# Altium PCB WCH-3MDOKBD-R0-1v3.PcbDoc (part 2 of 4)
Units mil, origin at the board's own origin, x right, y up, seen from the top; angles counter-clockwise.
Board outline 11710.74 x 4477.49 mil, 2 copper layers (Top Layer, Bottom Layer); 233 components, 145 nets, 545 pads, 1448 vias.
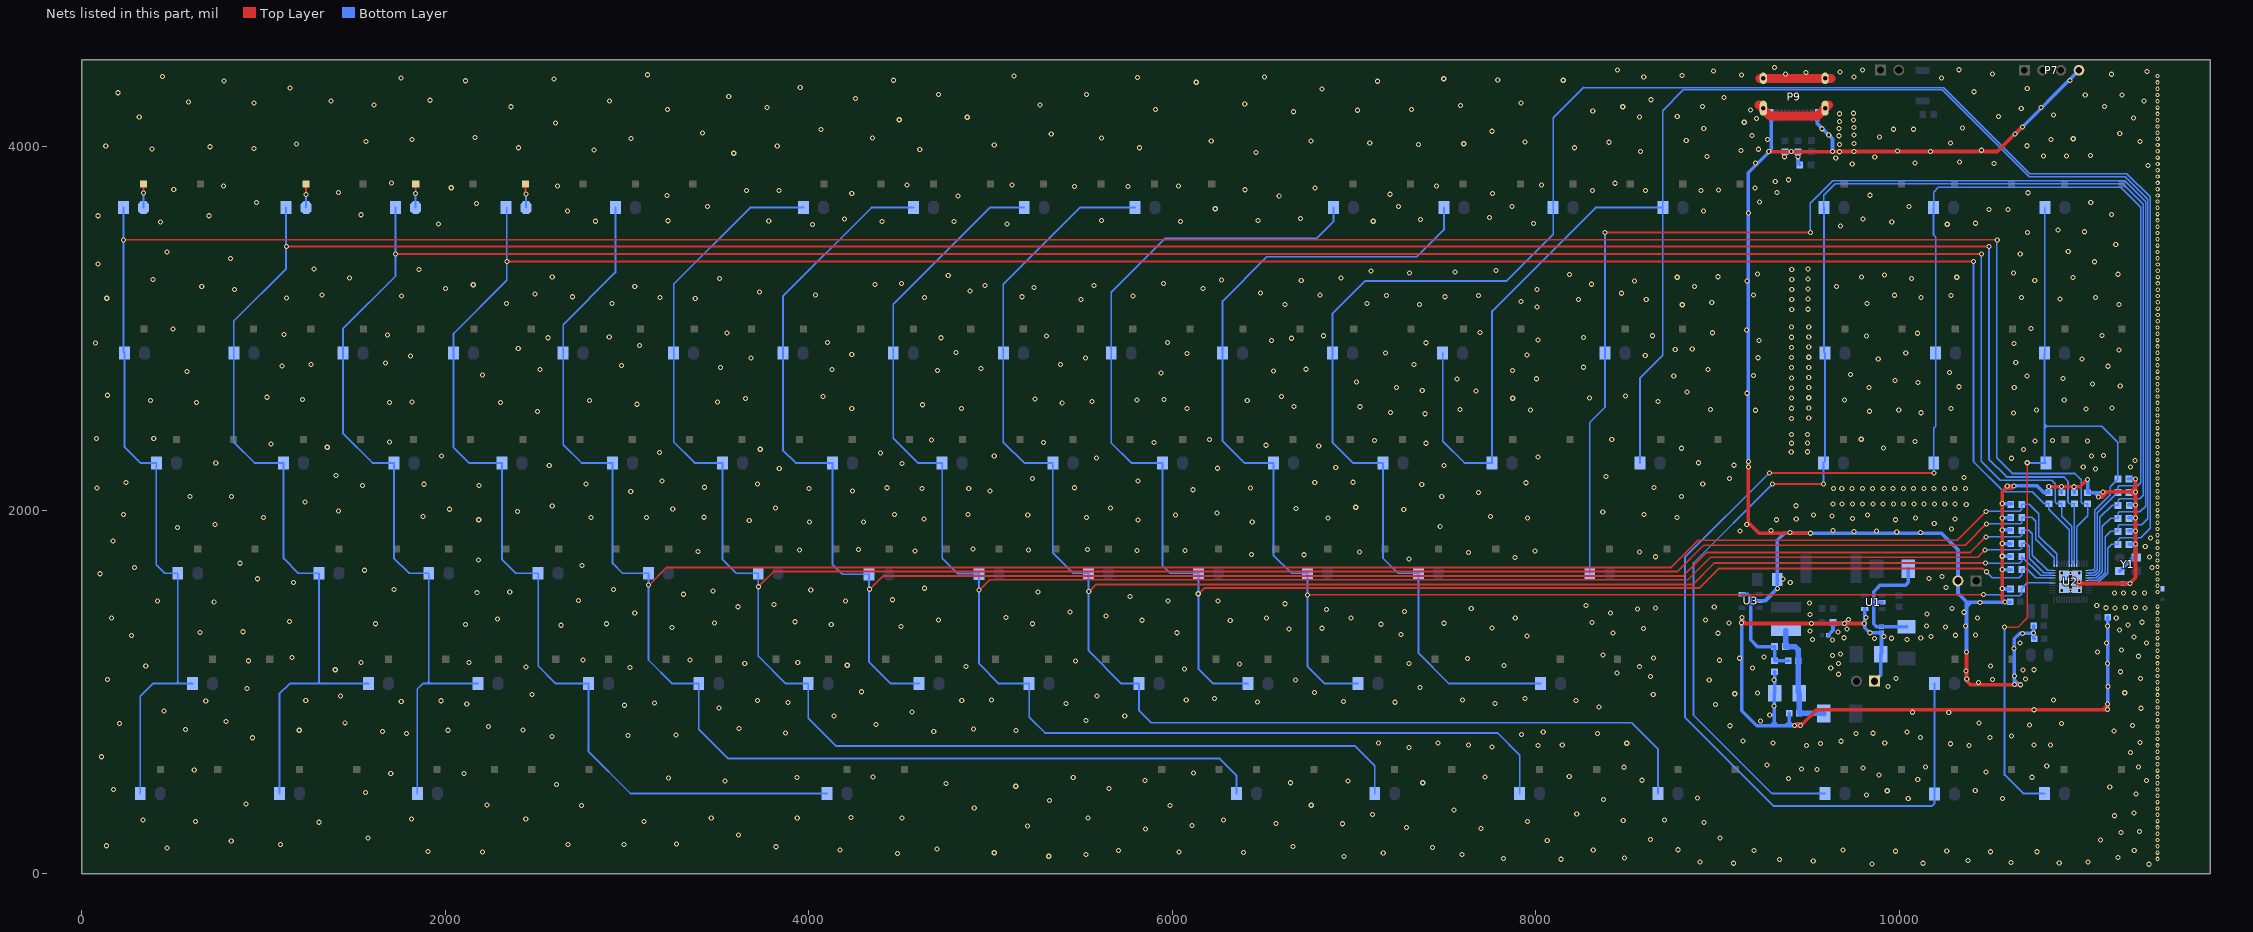
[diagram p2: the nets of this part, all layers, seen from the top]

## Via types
v1: diameter 28, hole 16, Top Layer to Bottom Layer, tented both sides, 1320 vias
v2: diameter 24, hole 12, Top Layer to Bottom Layer, tented both sides, 128 vias

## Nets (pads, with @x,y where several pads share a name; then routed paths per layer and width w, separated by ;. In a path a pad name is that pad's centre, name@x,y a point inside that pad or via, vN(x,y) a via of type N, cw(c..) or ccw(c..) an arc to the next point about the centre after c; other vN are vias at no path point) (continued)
BT-: C2.1 C3.1 C5.1 C6.1 C7.1 C8.1 C9.1 C11.2 C12.2 C13.2 C14.1 E1.0 J1.1 P7.4 P8.2 P9.0 P9.A1 P9.B1 R10.2 R11.2 R128.1 R129.1 R133.1 RJ1.1 RJ2.1 RJ3.1 RJ4.1 RJ5.1 RJ6.1 RJ7.1 RJ8.1 RJ9.1 RJ10.1 RJ11.1 RJ12.1 RJ13.1 RJ14.1 RJ15.1 RJ16.1 RJ17.1 U1.4 U2.0 U3.2 Y1.2 Y1.4 | length 18000.2
  Top Layer w20: v1(9134.61,1409.74) 9134.61,1395.68 ; v1@9168.65,2267.26 9168.65,1931.1 9227.54,1872.21 v1(9511.69,1872.21) ; v1(9281,3971.58) v1(9404.61,3971.58) v1@9636.45,3971.58 ; v1@9456.96,813.86 v1@9457.07,813.97 ; v1@9634.7,3972.2 10538.09,3972.2 v1@10675.48,4109.58 ; v1(9806.35,1376.09) v1(9697.77,1376.09) 9154.21,1376.09 ; v1(10368.6,1218.87) 10368.6,1061.6 10391.09,1039.11 v1@10670.69,1039.11 ; v1(10579.88,1493.79) 10565.71,1507.95 v1(10565.71,1567.63) v1(10565.71,1671.91) v1(10565.71,1745.7) v1(10565.71,1814.83) v1(10565.71,1890.97) v1(10565.71,1956.97) v1(10565.71,2035.15) 10565.71,2100.44 v1@10586.22,2120.95 ; v1(10593.28,2131.64) v1@10628.4,2131.64 ; v1@10595.1,2129.83 v1@10586.22,2120.95 ; v1(10629.12,2132.36) v1@10628.4,2131.64 ; v1(10821.17,2128.76) 10993.8,2128.76 v1(11034.05,2169.01) ; 10978.98,1596.12 11003.83,1596.12 ; v2@10988.26,1611.7 11003.83,1596.12 ; 10991.91,1584.2 11003.83,1596.12 ; v1@11120.34,2100.12 v1@11125.31,2100.12 ; v1(11145.36,934.11) v1@11145.36,926.02 ; v1(11298.76,2171.58) 11298.76,2124.66 ; 9134.61,1395.68 9134.61,1379.16 9131.54,1376.09 9154.21,1376.09 ; 9134.61,1395.68 9154.21,1376.09 ; v1@9457.07,813.97 v1(9423.52,813.97) 9434.27,824.73 9467.83,824.73 ; v1@9457.07,813.97 9467.83,824.73 ; 9467.83,824.73 9543.56,900.46 11119.8,900.46 ; v1@10586.22,2120.95 10617.7,2120.95 v1@10628.4,2131.64 ; 11003.83,1596.12 v1(11267.28,1596.12) 11298.76,1627.61 v1(11298.76,1814.3) v1(11298.76,1885.75) v1(11298.76,1957.21) v1(11298.76,2028.66) 11298.76,2075.34 ; 11119.8,900.46 v1@11145.36,926.02 ; 11119.8,900.46 11148.48,900.46 11145.36,903.58 v1@11145.36,926.02 ; v1@11125.31,2100.12 v1(11095.82,2070.63) 11116.06,2070.63 11145.55,2100.12 ; v1@11125.31,2100.12 11145.55,2100.12 ; 11145.55,2100.12 11273.98,2100.12 ; 11273.98,2100.12 11298.76,2075.34 ; 11273.98,2100.12 11274.22,2100.12 ; 11274.22,2100.12 11298.76,2124.66 ; 11274.22,2100.12 v1(11298.76,2100.12) ; 11298.76,2075.34 v1(11298.76,2100.12) ; v1(11298.76,2100.12) 11298.76,2124.66
  Top Layer w50: 9228.25,4229.01 9289.92,4167.33 9547.79,4167.33 P9.0@9608.53,4228.08 ; P9.0@9233.05,4374.91 P9.0@9251.14,4374.91 P9.0@9591.3,4374.91 9622.76,4374.91
  Bottom Layer w20: v1(9131.93,1379.85) v1@9131.93,1409.74 ; v1@9131.93,1380.56 9131.93,896.43 9214.5,813.86 9293.36,813.86 ; v1@9168.14,2236.74 9168.14,2989.83 9168.14,3259.66 9168.14,3855.24 9294.26,3981.36 P9.A1@9294.26,4172.15 ; U3.2@9228.25,1500.05 9260.48,1500.05 v1(9328.59,1568.15) C13.2@9328.59,1617.07 ; R133.1@9313.87,1111.26 9313.87,992.47 C12.2@9313.23,991.82 9310.83,989.42 9310.83,831.33 ; C13.2@9331.11,1614.55 C13.2@9328.59,1617.07 ; v1@9370.04,3942.53 R10.2@9370.04,3970.81 9370.94,3971.71 R11.2@9442.13,3971.71 v1@9442.13,3943.81 ; C11.2@9393.12,881.12 9393.12,832.42 ; v1(9442.47,3943.47) v1@9442.13,3943.81 ; R128.1@9452.55,3898.85 9442.13,3909.27 v1@9442.13,3943.81 ; v1@9456.96,813.86 v1@9411.68,813.86 ; P9.B1@9548.19,4172.15 9548.19,4125.84 9631.52,4042.51 v1@9631.52,3971.58 ; C5.1@9607.68,1311.74 9634.85,1338.91 R129.1@9634.85,1380.06 9635.78,1381 9640.69,1376.09 v1@9697.54,1376.09 ; v1(9697.77,1376.09) v1@9697.54,1376.09 ; v1(9720.27,1398.81) v1@9697.54,1376.09 ; U1.4@9809.52,1455.37 9809.52,1352.67 v1(9837.07,1325.11) C3.1@9901.41,1325.11 9901.41,1209.4 C2.1@9898.17,1206.15 9898.17,1093.77 J1.1@9863.17,1058.77 ; v1(10368.6,1218.87) 10368.6,1469.66 ; v1(10565.71,1567.63) 10567.31,1566.03 RJ11.1@10610.94,1566.03 ; v1(10565.71,1671.91) RJ10.1@10613.36,1671.91 ; v1(10565.71,1745.7) RJ9.1@10612.78,1745.7 ; v1(10565.71,1814.83) RJ8.1@10611.38,1814.83 ; v1(10565.71,1890.97) RJ7.1@10613.6,1890.97 ; v1(10565.71,1956.97) RJ6.1@10613.6,1956.97 ; v1(10565.71,2035.15) RJ5.1@10616.8,2035.15 ; v1@10593.28,2134.31 10756.38,2134.31 10794.53,2096.17 RJ4.1@10822.08,2096.17 v1@10822.08,2128.76 ; C6.1@10609.92,1491.87 10390.81,1491.87 ; v1(10635.72,4067.97) 10636.37,4067.97 P7.4@10987.53,4419.13 ; v1(10738.13,1323.21) v1@10725,1323.21 ; 10739.29,1343.8 10739.29,1337.5 ; C9.1@10739.29,1363.92 10739.29,1337.5 ; C8.1@10741.11,1292.32 10739.29,1294.13 C8.1@10739.29,1308.92 ; RJ3.1@10890.44,2095.09 v1(10890.44,2129.47) ; RJ2.1@10961.12,2095.45 v1(10961.12,2128.05) ; v1@11034.95,2172.09 RJ1.1@11034.95,2095.15 11075.48,2095.15 ; v1@11145.05,900.46 C14.1@11145.05,1410.61 ; Y1.4@11211.35,1663.76 11286.16,1738.56 Y1.2@11301.9,1738.56 11298.76,1741.7 11298.76,1796.97 ; C7.1@11228.28,1596.06 11267.21,1596.06 v1(11267.28,1596.12) ; RJ16.1@11259.59,2100.12 v1(11298.76,2100.12) ; RJ17.1@11260.2,2171.58 v1(11298.76,2171.58) ; RJ13.1@11260.51,1885.75 v1(11298.76,1885.75) ; RJ14.1@11260.82,1957.21 v1(11298.76,1957.21) ; RJ15.1@11262.03,2028.66 v1(11298.76,2028.66) ; RJ12.1@11263.19,1811.41 11284.33,1811.41 ; 9293.36,813.86 9309.38,813.86 ; 9293.36,813.86 9310.83,831.33 ; 9309.38,813.86 9328.3,813.86 ; 9309.38,813.86 9310.83,815.31 9310.83,831.33 ; 9310.83,831.33 9328.3,813.86 ; 9328.3,813.86 9375.1,813.86 ; C13.2@9328.59,1617.07 C13.2@9328.59,1618.92 ; C13.2@9328.59,1617.07 C13.2@9327.66,1618 C13.2@9328.59,1618.92 ; C13.2@9328.59,1618.92 9328.59,1834.58 9367.15,1873.15 10229.88,1873.15 10321.86,1781.17 P8.2@10321.86,1610.46 10321.86,1542.72 10372.71,1491.87 ; 9375.1,813.86 9392.63,813.86 ; 9375.1,813.86 9375.1,814.39 9393.12,832.42 ; 9392.63,813.86 v1@9411.68,813.86 ; 9392.63,813.86 9393.12,814.36 9393.12,832.42 ; 9393.12,832.42 v1@9411.68,813.86 ; 10368.6,1469.66 10368.6,1487.76 10372.71,1491.87 ; 10368.6,1469.66 10390.81,1491.87 ; 10372.71,1491.87 10390.81,1491.87 ; 10632.25,1065.98 10632.25,1291.64 10663.81,1323.21 v1@10725,1323.21 ; 10632.25,1065.98 v1(10632.25,1039.55) v1@10658.68,1039.55 ; 10632.25,1065.98 v1@10658.68,1039.55 ; v1@10658.68,1039.55 10666.25,1039.55 v1(10666.74,1039.06) 10659.17,1039.06 v1@10658.68,1039.55 ; v1@10725,1323.21 C8.1@10739.29,1308.92 ; v1@10725,1323.21 10739.29,1337.5 ; C8.1@10739.29,1308.92 10739.29,1337.5 ; 11075.48,2095.15 11096.31,2095.15 ; 11075.48,2095.15 11095.82,2074.81 v1(11095.82,2070.63) v1@11101.3,2076.11 ; 11096.31,2095.15 11120.34,2095.15 v1@11101.3,2076.11 ; 11096.31,2095.15 11101.3,2090.17 v1@11101.3,2076.11 ; 11284.33,1811.41 11298.76,1796.97 ; 11284.33,1811.41 11295.87,1811.41 v1(11298.76,1814.3) 11298.76,1796.97
  other v1: 11373.13,51.61 9849.9,53.57 9086.16,56.93 10129.34,56.86 10879.06,57.29 10613.6,60.68 8903.75,63.22 11036.8,63.54 9526.09,70.01 10377.75,71.35 9340.05,77.71 8138.58,79.24 7821.83,82.09 8487.25,85.73 11201.46,87.93 6945.26,93.81 5320.47,95.42 7593.91,104.38 5525.36,105.47 4489.49,111.29 5020.42,114.86 7160.4,114.45 6390.92,115.13 2205.95,118.41 6037.59,118.17 10499.89,120.21 10755.97,120.21 1905.1,121.77 9979.16,123.17 10260.01,125.38 11291.42,126.83 5703.24,127.32 9200.69,127.63 9690.04,129.22 4172.96,130.96 8315.43,130.4 8781.77,131.21 4706.54,136.45 470.41,141.18 7430.58,143.5 3819.52,147.6 6665.04,148.63 136.5,153.36 1094.31,160.35 2676.82,160.11 2982.85,160.11 3271.98,163.36 823.46,178.35 8062.78,183.18 11105.17,185.53 8630.18,187.51 1576.73,195.31 9012.13,195.84 3614.38,211.7 11217.75,226.59 11319.47,230.64 5852.5,246.23 7698.76,247.92 7288.88,252.82 5203.02,261.33 6107.87,263.72 6937.13,274.35 6570.7,275.88 8925.21,281.28 1305.86,282.43 625.89,286.2 3094.58,286.4 7953.78,286.91 8480.76,291.46 338.28,296.03 6280.78,295.65 8707.66,295.79 1814.44,300.18 2443.66,300.98 5537.18,304.85 3463.75,305.83 4513,305.83 3936.8,306.78 4233.66,309.19 11182.04,318.1 7100.41,324.88 8224.94,328.47 11289.32,333.78 7549.25,349.97 4910.61,361.84 2749.69,373.84 5986.89,374.29 6764.41,376.17 2230.78,377.97 905.55,384.08 5324.85,401.44 8371.47,407.79 10048.63,413.47 10567.34,413.8 8888.86,415.37 9819.4,433.17 11302.37,437.41 1562.74,447 9932.75,455.64 10416.91,456.67 176.56,462.83 5650.76,468.45 11157.08,477.43 5139.06,480.63 2613.67,490.42 4755.88,495.28 6649.77,499.9 7377.84,499.9 3539.61,509.19 6966.03,509.79 5849.17,511.78 11358.51,511.75 8584.95,513.65 10100.88,516.97 9390.47,523.09 3227.75,526.05 5455.14,527.76 3934.94,529.28 7719.46,530.66 10729.05,530.22 4354.34,531.24 8183.47,535.31 9887.13,542.68 1701.01,551.66 2104.85,551.66 6116.06,552.62 10475.38,558.05 619.68,568.9 9545.69,572.57 9461.99,575.74 9799.4,580.66 8484.62,585.22 11314.23,585.66 10142.28,586.6 10810.22,592.75 9271.72,597.08 108.53,642.76 11271.53,666.91 7301.89,694.42 7757.67,697.32 8012.44,704.11 10381.9,704.88 9487.62,705.88 7628.58,707.51 8144.92,707.51 10830.65,707.58 10739.2,708.6 10279.84,714.38 9564.8,716.56 7134.27,717.7 7462.13,717.7 8499.8,717.12 9919.43,717.78 9303.34,718.61 11323.65,720.79 9678.02,727.98 9138.4,729.57 940.04,747.56 10116.87,748.68 10497.53,749.77 2586.9,755.26 10617.48,756.63 3007,760.38 3269.89,762.05 7920.72,765.26 1787.68,770.63 8338.85,770.58 9761.6,770.63 9855.2,772.13 3873.21,773.34 10041.84,778.98 8040.43,779.53 1654.47,780.88 4687.87,781.88 11180.09,784.77 5139.73,786.46 1197.35,788.68 2016.12,788.49 571.64,791.92 2428.07,791.12 4906.46,796.45 3616.28,797.32 2239.14,809.07 9067.33,813.5 9455.5,814.5 11283.08,814.42 10714.38,816.53 4371.05,820.56 207.95,826.23 10891.79,826.46 10437.65,828.27 1450,829.66 794.83,837.25 9236.36,840.13 5526.01,843.17 4139.53,866.71 5738.64,867.97 9286.57,872.27 10271.34,886.09 10072.44,887.78 4569.18,889.24 452.37,893.93 10740.55,901.38 11145.36,902.75 11328.34,909.61 3506.9,911.12 8346.79,915.86 9309.43,921.71 2987.53,926.41 8987.7,929.78 2118.99,932.41 5416.15,935.3 7774.65,935.11 3151.89,939.06 3886.11,941.53 7225.45,942.87 6468.27,944.71 1758.39,947.2 6942.44,947.67 682.93,949.14 1976.89,950.96 3717.4,951.86 4842.05,953.02 1233.08,953.42 8219.69,953.42 10847.65,954.09 5005.03,955.79 6076.55,955.28 7596.33,955.28 6232.11,964.26 7940.38,964.26 1424.01,976.98 5586.8,977.11 2477.6,985.41 8645.59,986.3 9094,989.64 9219.81,993.63 11239.35,994.79 6782.59,997.17 4289.55,1000.47 909.85,1019.13 7362.98,1024.09 9937.57,1029.98 11147,1029.42 10434.23,1051.67 9309.53,1063.96 8953.66,1064.75 6677.88,1065.98 10511.4,1067.14 142.96,1068.71 10370.12,1069.9 10693.81,1071.54 9981.07,1072.41 11325.92,1074.44 8629.49,1083.88 10633.28,1087.45 9663.72,1096.52 8445.56,1104.42 11215.11,1110.22 10366.83,1113.89 10680.41,1119.14 1395.37,1121.39 10740.53,1121.58 6067.57,1125.81 9622.23,1130.32 9191.61,1131.1 3017.03,1132.92 2443.88,1137.13 4864.93,1138.54 8571.14,1138.21 353.16,1141.93 10500.89,1142.16 7823.7,1143.76 4211.82,1146.2 6369.73,1152.74 3648.34,1155.91 7303.15,1155.73 11143.54,1155.24 9663.72,1156.3 3939.8,1160.77 1537.8,1162.42 2131.55,1162.08 5468.01,1169 918.28,1170.85 9009.94,1173.57 2759.28,1174.82 3347.52,1174.82 7623.26,1182.65 9120.55,1184.85 8647.6,1185.5 1157.32,1188.52 9254.86,1191.1 11315.44,1195.64 9630.99,1199.82 8369.06,1202.26 9675.22,1209.14 11090.44,1219.88 11222.04,1229.12 10629.83,1238.91 10662.53,1268.64 11358.65,1268.24 11140.08,1269.52 9632.01,1285.2 10042.11,1286.93 9521.01,1288.52 9863.09,1293.31 9957.12,1294.85 10117.13,1295.39 9694.33,1297.57 11289.94,1301.18 10173.05,1303.25 9914.57,1304.34 7950.36,1307.4 275.22,1309.62 10307.72,1311.49 10419.24,1312.41 7258.94,1314.5 10677.97,1319.83 9002.39,1322.49 8424.22,1323.63 6025.69,1325.13 650.55,1327.17 9661.25,1329.42 887.3,1330.6 9508.71,1334.13 11211.35,1339.61 6642.32,1346.39 9711.82,1346.48 8591.75,1347.98 6823.05,1349.93 7757.98,1350.02 3246.97,1353.28 10252.81,1356.64 4508.1,1359.8 10149.02,1361.02 10363.7,1361.33 11144.69,1363.02 2636.84,1366.08 11257.08,1367.56 2112.04,1370.35 4123.86,1370.05 7147.85,1371.7 1617.1,1374.62 2888.57,1374.62 5231.92,1374.51 9515.86,1376.4 7494.61,1377.11 3481.64,1378.88 9062.26,1379.5 8308.37,1381.56 11334.58,1382.81 3924.05,1385.42 1143.49,1387.42 6318.88,1392.07 5834.26,1393.94 8932.39,1394.94 4713.03,1395.66 2286.97,1400.22 165.02,1405.9 6519.32,1407.03 6983.03,1407.03 7886.53,1407.03 10430.29,1406.39 11192.46,1406.55 5086.19,1408.51 9815.53,1408.18 5635.1,1418.22 9507.59,1426.18 10152.7,1428.96 3043.26,1432.72 8410.43,1433.97 10355.89,1437.85 5438,1438.71 7276.67,1442.07 6847.86,1452.7 8559.39,1456.04 7644.74,1457.86 10290.24,1457.67 8658.77,1460.48 11186.79,1461.24 11349.89,1461.71 11135.56,1462.65 11242.26,1463.59 11298.19,1464.06 8981.07,1466.23 3611.57,1467.84 8275.26,1475.34 11085.27,1475.81 3808.88,1479.74 6621.06,1484.6 9506.22,1489.26 10442.56,1490.53 729.62,1494.08 416.93,1498.56 5976.08,1498.78 6252.5,1498.78 4202.29,1499.05 2733.89,1501.72 4460.53,1506.29 5766.99,1523.58 3310.97,1536.75 11182.77,1543.07 11232,1543.07 11289.42,1543.07 11348,1543.96 2176.04,1545.28 2355.24,1549.55 5261.81,1549.74 3473.11,1553.82 4011.15,1559.6 1719.5,1562.35 2926.97,1562.35 4636.18,1569.85 10256.18,1574.1 1164.83,1600.75 9399.25,1600.5 9359.88,1620.18 968.56,1622.08 10162.22,1623.47 10233.97,1633.82 101.54,1649.52 1557.36,1669.02 290.3,1684.48 11389.96,1684.11 2752.04,1694.62 870.43,1707.42 2184.57,1724.48 7302.6,1731.42 7884.77,1738.16 11375.64,1742.09 8658.77,1743.3 6724.94,1753.89 6434.99,1756.14 7628.53,1767.38 8570.17,1768.1 7030.63,1769.63 3392.04,1771.42 4584.39,1774.51 7996.07,1775.19 5805.14,1777.49 6070.13,1777.49 3950.19,1780.47 5209.65,1780.47 4274.73,1783.44 5534.19,1783.44 4902.97,1786.42 11352.31,1799.29 173.66,1829.22 11381.75,1845.94 9397.3,1875.76 10115.79,1876.36 9984.97,1879.87 9750.63,1882.93 9123,1883.66 9874.13,1884.36 9294.24,1886.86 9634.08,1887.56 10286.47,1896.46 527.02,1903.58 7473.77,1908.76 732.88,1920.74 9159.81,1920.46 10191.4,1925.87 4005.31,1934.03 4301.58,1933.48 6439.61,1933.47 3672.76,1942.18 5810.63,1945.62 2184.65,1946.71 9323.61,1946.78 9978.16,1946.78 4634.13,1951.42 9432.43,1951.58 10306.7,1951.6 9742.49,1952.36 10088.03,1955.67 6855.91,1957.03 7954.45,1956.19 2801.84,1958.48 8775.68,1958.12 999.87,1959.95 3107.7,1959.56 5527.62,1959.22 3422.87,1960.11 1877.35,1963.42 7751.33,1964.27 9628.3,1968.03 5205,1971.7 6018.59,1973.73 9527.59,1973.4 9824.31,1973.57 4472.24,1974.58 4876.97,1974.58 230.21,1975.45 8593.9,1976.25 6244.87,1984.83 8367.88,1989.44 2397.68,1991.03 1414.4,1993.66 7273.39,2003.39 2024.84,2004.21 3251.9,2006.48 6679.98,2007.88 5660.82,2010.45 3817.65,2011.72 7009.19,2015.54 2589.39,2022.22 9430.83,2023.6 10367.37,2029.38 9635.57,2032.46 9684.25,2032.46 9740.74,2032.46 9797.22,2032.46 9853.7,2032.46 9910.18,2032.46 9966.67,2032.46 10023.15,2032.46 10079.63,2032.46 10136.12,2032.46 10192.6,2032.46 10249.08,2032.46 10305.56,2032.46 1229.71,2045.33 7482.23,2073.46 597.36,2074.35 8801.33,2074.63 825.52,2075.13 7683.75,2097.02 11120.14,2099.7 3020.77,2101.55 4240.03,2105 4997.03,2104.45 6114.97,2111.49 9682.71,2118.47 9739.19,2118.47 9795.67,2118.47 9852.16,2118.47 9908.64,2118.47 9965.13,2118.47 10021.61,2118.47 10078.09,2118.47 10134.58,2118.47 10191.06,2118.47 10247.54,2118.47 10304.03,2118.47 10362.42,2118.7 4002.42,2119.49 4622.54,2119.49 4880.45,2119.49 9636.18,2119.24 85.35,2121.29 6429.94,2121.73 4431.28,2122.39 5462.9,2122.39 8649.7,2123.05 3425.76,2125.29 1544.62,2134.52 2187.13,2134.52 7372.41,2140.46 1883.18,2141.94 3718.44,2142.67 2774.39,2143.75 8917.99,2144.06 243.93,2150.44 7946.82,2150.11 6783.5,2152.52 6994.7,2153.1 3193.95,2160.06 5810.63,2160.06 9065.17,2172.89 5231.08,2174.55 10355.67,2178.81 8386.16,2184.05 1399.26,2189.69 11079.57,2226.43 3837.94,2229.05 6247.72,2229.75 6899.35,2234.58 9169.88,2236.74 11011.16,2236.97 11272.09,2236.97 2572.82,2245.02 7495.49,2244.24 9090.5,2246.18 4513,2256.9 738.16,2257.82 8893.6,2259.99 9170.61,2267.26 11295.93,2273.36 10616.58,2284.84 5583.97,2287.1 8011.83,2291.77 1979.75,2296.22 5020.42,2297.35 11055.47,2298.33 11123.09,2298.97 4395.39,2312.72 3178.7,2317.55 9404.7,2319.92 9494.86,2320.51 10681.36,2332.11 3733.37,2334.62 8801.62,2339.81 9911.68,2342.12 1351.26,2345.42 6805.86,2351.78 6515.9,2356.28 1041.17,2362.51 7394.77,2367.52 9405.21,2367.58 9494.95,2369.61 5290.86,2371.35 5898.78,2371.86 1694.56,2375.42 10086,2377.03 10745.79,2379.4 11034.6,2380.22 10842.12,2383.01 7111.57,2383.44 4676.46,2386.42 8417.32,2387.76 6205.65,2388.96 9789.86,2389.52 81.09,2394.35 397.27,2394.17 9406,2414.63 9494.86,2414.82 9407.3,2504.19 9501.33,2505.99 7390.52,2529.61 10627.22,2532.9 10119.1,2535.45 7201.04,2536.27 2508.83,2543.07 9834.8,2543.61 7970.72,2549.78 9208.7,2549.06 9996.24,2549.76 10754.59,2550.95 7583.6,2553.75 8959.98,2553.99 11025.91,2555.25 10284.23,2557.6 4236.57,2558.63 4841.1,2558.63 6080.93,2558.63 9407.3,2559.96 9501.33,2561.77 11169.07,2562.13 7033.31,2568.23 6668.75,2569.81 4625.93,2579.12 3054.97,2582.09 5394.42,2589.37 1693.9,2590.62 2304.04,2590.62 632.76,2591.69 1817.63,2594.89 3498.83,2594.49 8671.48,2596.79 5558.52,2597.62 379.76,2603.42 2794.7,2603.42 6412.51,2603.53 10906.62,2604.62 5806.38,2605.78 9697.87,2606.04 1216.39,2607.33 5955.36,2607.47 5245.84,2609.86 3652.96,2613.97 7872.76,2614.84 9407.3,2615.74 8296,2617.43 9501.33,2617.54 1019.76,2620.49 6601.32,2623.76 4077.74,2625.23 8493.91,2628.26 143.46,2631.23 9162.32,2642.25 8831.93,2650.03 7670.17,2655.55 7374.81,2656.95 9407.3,2671.52 7232.41,2673.84 9501.33,2673.32 9832.87,2673.76 10631.72,2674.54 10328.53,2678.42 11214.58,2682.91 11060.88,2693.06 10100.98,2702.59 7012.78,2705.22 9975.35,2712.4 7566.7,2720.28 8004.11,2722.29 10900.45,2723.91 9407.3,2727.3 9501.33,2729.1 8758.67,2736.7 10700.94,2736.25 9197.89,2741.14 2204.87,2743.23 9730.44,2744.88 5937.48,2753.31 10274.81,2757.4 580.29,2761.29 6556.36,2765.36 4707.9,2768.68 7872.29,2768.68 4128.98,2773.8 8947.67,2773.15 2521.64,2774.09 6736.18,2774.35 4948.69,2778.93 9407.3,2783.07 3514.19,2784.05 9501.33,2784.88 8262.4,2785.6 11146.31,2790.81 1102.1,2791.99 2969.64,2795.42 1262.96,2799.69 5385.07,2801.69 7329.58,2801.33 1672.57,2808.22 10639.86,2811.65 11004.12,2829.98 9883.49,2831.47 3683.26,2835.28 5522.49,2835.28 9222.46,2837.58 9407.3,2838.85 9501.33,2840.65 1809.1,2846.62 8601.8,2850.78 7952.17,2852.14 4236.57,2855.78 6080.93,2860.9 10034.53,2863.69 7172.24,2864.26 4810.36,2866.02 11207.24,2879.31 8766.78,2882.44 8860.29,2886.74 2402.17,2889.29 9407.3,2894.63 9501.33,2896.43 3068.93,2904.27 10629.47,2915.12 76.82,2919.16 7394.76,2920.46 4103.36,2922.38 5973.33,2922.38 6545.12,2931.7 9227.31,2932.25 8011.3,2936.51 6655.27,2945.18 2566.4,2947.99 4728.39,2947.99 8262.4,2949.68 9407.3,2950.41 2902.93,2951.59 9501.33,2952.21 9818.42,2956.81 5307.32,2958.24 6832.84,2958.67 8642.26,2958.67 11114.38,2959.11 1682.73,2962.97 1112.59,2965.65 10098.32,2972.77 3550.06,2973.61 8972.3,2975.08 7692.21,2976.11 9159.3,2989.83 502.72,2996.14 10722.65,2998.28 9407.3,3006.18 9501.33,3007.99 9407.49,3102.44 9497.02,3104.73 8006.99,3117.91 7360.33,3129.99 8805.38,3129.1 6619.09,3130.81 11207.24,3131.76 7071.93,3135.4 9821.39,3135.56 2337.28,3137.25 2918.44,3137.24 8967.37,3142.53 7918.34,3147.46 9407.49,3157.52 5496.88,3158.05 8235.42,3158.72 8607.44,3158.89 9497.02,3159.82 10883.7,3160.78 3375.87,3163.17 138.52,3165.01 1126.81,3166 3181.19,3168.29 4636.18,3168.29 10119.41,3169.79 11077.67,3169.08 10672.15,3170.22 2699.6,3173.41 5174.12,3173.42 7500.05,3173.42 1759.61,3177.36 5783.78,3178.54 7684.4,3179.47 10283.99,3179.62 7178.13,3181.26 9973.75,3181.46 1322.69,3183.69 4036.76,3183.66 6813.54,3183.66 9197.87,3183.69 2494.67,3188.78 8471.43,3192.43 6485.8,3194.56 3729.37,3199.03 4887.22,3204.15 9407.49,3212.61 840.55,3213.56 8006.99,3213.94 9497.02,3214.91 2001.09,3217.82 6168.02,3219.52 5238.32,3224.82 3042.86,3229.77 9654.16,3229.22 661.35,3230.62 8871.52,3230.64 4969.19,3234.89 5568.61,3234.89 2154.69,3239.16 4364.64,3240.02 8305.1,3241.88 4511.05,3245.62 5952.62,3246.72 8543.59,3258.93 9160.93,3259.66 6709.62,3263.55 10744.42,3263.79 6270.48,3265.63 9407.49,3267.7 392.55,3269.02 9497.02,3269.99 3509.84,3273.99 10067.38,3273.24 6929.15,3275.7 1473.53,3276.16 10953.93,3279.23 8777.75,3280.43 10315.2,3280.59 2589.39,3281.48 9790.18,3282.42 9002.39,3283.32 4767.57,3289.65 9918.9,3293.44 8184.29,3295.21 9218.58,3297.66 11202.9,3297.16 7305.93,3303.83 10626.9,3303.91 7554.23,3310.42 7092.78,3314.81 7780.56,3317.01 9407.49,3322.78 1855.99,3323.16 1277.75,3325.64 9497.02,3325.08 89.61,3354.36 11073.22,3365.61 819.22,3384.22 10664.63,3408.88 469.35,3418.36 10928.68,3421.94 11189.84,3459.66 10705.25,3526.4 11017.19,3530.75 10872.1,3539.46 9676.84,3563.11 4020.33,3571.5 10263.09,3572.33 1963.05,3573.9 5091.79,3573.13 7987.11,3576.3 10418.9,3577.83 9957.49,3583.79 433.47,3584.07 4403.62,3587.22 4798.47,3587.22 6045.06,3587.22 2827.68,3588.39 7105.57,3588.39 3780.32,3590.04 3225.74,3591.22 5610.73,3592.87 6470.4,3593.63 7365.26,3598.27 4197.73,3601.32 9798.56,3601.34 6705.96,3603.76 7745.97,3608.89 89.61,3618.89 701.55,3619.13 1536.64,3624.26 11166.62,3626.51 9170.68,3633.53 2673.99,3644.75 8922.61,3644.1 10493.42,3654.07 10596.44,3654.07 6236.48,3657.63 10053.34,3669.16 3442.47,3670.36 7243.89,3670.37 7868.93,3670.37 2171.91,3685.73 962.84,3690.86 11052.36,3691.23 9229.7,3695.46 4820.61,3726.72 6588.12,3726.72 3220.8,3729.46 9838.88,3731.48 7197.78,3736.97 4236.57,3742.09 7761.33,3742.09 9326.11,3745.92 10706.7,3745.47 1413.68,3747.21 3657.64,3757.46 3836.96,3757.46 8312.34,3758.16 8604.17,3758.5 8908.7,3758.5 9004.31,3760.62 506.87,3762.58 6400.43,3762.09 9206.33,3770.83 2033.58,3772.83 6784.21,3772.23 5461.26,3779.01 5757.4,3779.01 780.82,3781.63 6033.79,3781.83 7453.15,3782.85 2617.63,3783.07 5117.17,3787.47 8031.06,3787.25 4541.45,3788.11 8435.47,3797.56 1705.07,3798.38 9317.04,3806.62 9389.59,3817.08 11367.08,3894.65 9740.18,3904.16 10520.32,3905.38 9208.12,3909.49 10086.35,3909.49 10331.11,3915.66 9649.62,3935.8 9864.22,3942.4 9368.29,3943.47 8941.72,3945.84 10918.97,3947.66 10791.78,3948.59 11050.6,3949.71 3587.61,3962.86 6460.04,3967.51 9669.83,3970.72 9750.13,3971.45 8575.93,3972.64 9631.67,3972.96 10169.88,3973.26 9989.13,3974.85 9128.67,3978.87 10450.39,3979.42 2819.2,3980.34 4610.56,3982.88 9224.46,3984.92 388.13,3985.45 947.47,3988 2402.45,3993.13 5819.64,3993.13 8212.18,3993.13 706.68,3998.25 132.88,4003.37 3826.71,4003.37 10702.34,4003.73 5020.41,4008.5 7354.67,4010.18 9670.04,4011.1 1183.13,4013.62 7603.1,4015.05 9750.97,4016.59 10280.92,4018.74 7086.31,4019.86 8403.11,4023.02 7940.65,4023.87 11323.13,4026.53 1563.99,4027.34 6762.31,4028.99 6214.29,4030.02 8827.24,4032.51 9273.94,4037.55 10834.65,4038.16 1818.41,4039.23 10956,4042.27 3022.86,4043.08 4350.51,4046.64 5609.86,4046.65 2164.47,4049.14 9889.25,4051.68 9667.42,4059.17 9188.87,4060.84 9610.93,4063.05 9749.48,4063.1 5334,4067.64 11211.66,4071.01 3415.37,4073.4 7758.59,4083.61 4068.39,4092.44 9966.99,4094.67 10077.16,4094.67 8923.73,4097.93 9574.19,4097.26 9667.86,4098.5 10346.01,4101.66 9749.48,4105.13 10677.8,4107.26 2607.69,4129.58 9146.36,4133.22 9669.61,4137.39 9747.4,4144.67 4497.85,4146.82 9214.43,4153.55 11287.36,4156.86 4872.25,4160.59 317.31,4162.19 8570.8,4162.19 8777.87,4164.42 10545.62,4164.29 10846.99,4173.9 9669.35,4179.84 9747.65,4182.94 6667.14,4191.01 8312.76,4195.21 7019.14,4199.2 9180.09,4201.33 3222.17,4203.18 5906.74,4203.18 7315.62,4203.18 10670.11,4208.86 3770.35,4213.42 10779.46,4213.89 2361.47,4218.55 8477.72,4218.52 8917.19,4218.94 11128.75,4219.15 7586.05,4224.51 1608.36,4228.79 5271.45,4228.79 6398.56,4233.92 947.47,4239.04 7917.97,4240.09 588.84,4244.16 1372.69,4249.29 2904.53,4249.29 11346.26,4251.12 1915.75,4254.41 8633.74,4256.93 4257.06,4264.66 9034.95,4268.47 3560.3,4274.9 11224.89,4282.58 11022.32,4283.5 4713.02,4285.15 5527.61,4285.15 199.48,4295.39 10410.19,4301.07 6823.79,4315.89 10703.02,4319.93 1147.27,4321.01 3953.48,4324.88 6131.81,4353.28 7129.65,4358.83 782.55,4360.44 2111.6,4361.44 10938.19,4363.55 4467.09,4364.23 7790.47,4364.69 8150.61,4364.44 2599.39,4370.55 7493.36,4372.66 1757.6,4376.7 10232.4,4376.22 5807.6,4379.3 6507.52,4382.57 8593.62,4383 9749.04,4382.54 446.09,4385.95 5128.77,4387.18 8804.35,4390.65 9130.28,4393.34 3112.28,4394.62 11165.76,4397.45 10512.08,4399 9374.31,4399.42 9486.06,4406.76 9673.87,4410.31 11362.1,4413.15 8977.69,4415.18 8449.96,4419.97 9796.35,4421.62 10326.88,4421.91 9313.27,4433.47
  other v2: 11419.5,80.86 11419.5,115.56 11419.5,150.26 11419.5,184.96 11419.5,219.66 11419.5,254.36 11419.5,289.07 11419.5,323.77 11419.5,358.47 11419.5,393.17 11419.5,427.87 11419.5,462.57 11419.5,497.28 11419.5,531.98 11419.5,566.68 11419.5,601.38 11419.5,636.08 11419.5,670.78 11419.5,705.49 11419.5,740.19 11419.5,774.89 11419.5,809.59 11419.5,844.29 11419.5,878.99 11419.5,913.7 11419.5,948.4 11419.5,983.1 11419.5,1017.8 11419.5,1052.5 11419.5,1087.2 11419.5,1121.91 11419.5,1156.61 11419.5,1191.31 11419.5,1226.01 11419.5,1260.71 11419.5,1295.42 11419.5,1330.12 11419.5,1364.82 11419.5,1399.52 11419.5,1434.22 11419.5,1468.92 11419.5,1549.49 10940.73,1557.7 11419.5,1583.53 10892.73,1605.7 10988.73,1605.7 11419.5,1618 11419.5,1652.7 10940.73,1653.7 11419.5,1687.4 11419.5,1722.1 11419.5,1756.8 11419.5,1791.51 11419.5,1826.21 11419.5,1860.91 11419.5,1895.61 11419.5,1930.31 11419.5,1965.01 11419.5,1999.72 11419.5,2034.42 11419.5,2069.12 11419.5,2103.82 11419.5,2138.52 11419.5,2173.22 11419.5,2207.93 11419.5,2242.63 11419.5,2277.33 11419.5,2312.03 11419.5,2346.73 11419.5,2381.43 11419.5,2416.14 11419.5,2450.84 11419.5,2485.54 11419.5,2520.24 11419.5,2554.94 11419.5,2589.65 11419.5,2624.35 11419.5,2659.05 11419.5,2691.99 11419.5,2726.7 11419.5,2761.4 11419.5,2796.1 11419.5,2830.8 11419.5,2865.5 11419.5,2900.2 11419.5,2934.91 11419.5,2969.61 11419.5,3004.31 11420.84,3038.56 11420.84,3073.27 11420.84,3107.97 11420.84,3142.67 11420.84,3177.37 11420.84,3212.07 11420.84,3246.77 11420.84,3281.48 11420.84,3316.18 11420.84,3350.88 11419.52,3385.13 11419.52,3419.84 11419.52,3454.54 11419.52,3489.24 11419.52,3523.94 11419.52,3558.64 11419.52,3593.35 11419.52,3628.05 11419.52,3662.75 11419.52,3697.45 11420.17,3730.4 11420.17,3765.1 11420.17,3799.81 11420.17,3834.51 11420.17,3869.21 11420.17,3903.91 11420.17,3938.61 11420.17,3973.31 11420.17,4008.02 11420.17,4042.72 11419.52,4075 11419.52,4109.71 11419.52,4144.41 11419.52,4179.11 11419.52,4213.81 11419.52,4248.51 11419.52,4283.21 11419.52,4317.92 11419.52,4352.62 11419.52,4387.32
CL0: D1.2 D7.2 D13.2 D19.2 D28.2 D34.2 RJ1.2 U2.20 | length 16250.2
  Top Layer w10: v1(230.35,3486.47) v1(10538.01,3486.47)
  Bottom Layer w7: U2.20@10975.43,1704.68 10975.43,1908.63 11034.95,1968.16 RJ1.2@11034.95,2034.52
  Bottom Layer w10: D1.2@230.22,3664.02 230.22,2869.68 D7.2@236.44,2863.47 236.44,2346.22 323.49,2259.16 D13.2@411.11,2259.16 411.11,1699.56 458.76,1651.91 D19.2@528.99,1651.91 528.99,1054.33 ; D34.2@322.75,440.87 322.75,976.26 391.71,1045.22 519.88,1045.22 ; D28.2@610.9,1045.22 538.09,1045.22 ; v1@10535.73,3486.47 10535.73,2288.01 10623.45,2200.29 10965.77,2200.29 10999.82,2166.25 10999.82,2043.1 11008.4,2034.52 RJ1.2@11034.95,2034.52 ; 519.88,1045.22 528.22,1045.22 ; 519.88,1045.22 528.99,1054.33 ; 528.22,1045.22 538.09,1045.22 ; 528.22,1045.22 528.99,1045.99 528.99,1054.33 ; 528.99,1054.33 538.09,1045.22
CL1: D2.2 D8.2 D14.2 D20.2 D29.2 D35.2 RJ2.2 U2.19 | length 15692.5
  Top Layer w10: v1(1127.92,3449.57) v1@10494.72,3449.57
  Bottom Layer w7: U2.19@10961.65,1704.68 RJ2.2@10961.65,2034.75
  Bottom Layer w10: D35.2@1088.31,440.87 1088.31,988.32 1145.22,1045.22 1295.04,1045.22 ; D2.2@1125.34,3664.02 1125.34,3327.9 837.44,3040 D8.2@837.44,2863.47 837.44,2373.14 951.43,2259.16 D14.2@1111.16,2259.16 1111.16,1733.71 1192.96,1651.91 D20.2@1306.18,1651.91 1306.18,1056.36 ; D29.2@1578.84,1045.22 1317.32,1045.22 ; v1(10491.96,3448.86) 10491.96,2279.86 10589.59,2182.23 10903.4,2182.23 10927.11,2158.52 10927.11,2043.02 10935.39,2034.75 10961.65,2034.75 RJ2.2@10963.33,2034.75 ; 1295.04,1045.22 1308.39,1045.22 ; 1295.04,1045.22 1306.18,1056.36 ; 1306.18,1056.36 1306.18,1047.43 1308.39,1045.22 ; 1306.18,1056.36 1317.32,1045.22 ; 1308.39,1045.22 1317.32,1045.22
CL2: D3.2 D9.2 D15.2 D21.2 D30.2 D36.2 RJ3.2 U2.18 | length 14833.7
  Top Layer w10: v1@1729.53,3409.04 10450.8,3409.04 v1@10453.09,3409.04
  Bottom Layer w7: RJ3.2@10893.01,2035.35 10893.01,1964.59 10947.87,1909.74 U2.18@10947.87,1704.68
  Bottom Layer w10: D3.2@1727.53,3664.02 v1(1727.53,3407.63) 1727.53,3287.33 1437.66,2997.46 D9.2@1437.66,2863.47 1437.66,2421.93 1600.44,2259.16 D15.2@1718.18,2259.16 1718.18,1735.34 1801.6,1651.91 D21.2@1909.59,1651.91 1909.59,1056.25 ; D36.2@1847.05,440.87 1847.05,1015.38 1876.89,1045.22 1898.57,1045.22 ; D30.2@2180.6,1045.22 1920.62,1045.22 ; v1@10450.03,3409.04 10450.03,3408.01 10450.03,2268.49 10554.22,2164.31 10836.88,2164.31 10857.25,2143.94 10857.25,2044.56 10866.45,2035.35 RJ3.2@10893.01,2035.35 ; 1898.57,1045.22 1910.11,1045.22 ; 1898.57,1045.22 1909.59,1056.25 ; 1909.59,1056.25 1909.59,1045.74 1910.11,1045.22 ; 1909.59,1056.25 1920.62,1045.22 ; 1910.11,1045.22 1920.62,1045.22
  other v1: 10450.8,3408.01
CL3: D4.2 D10.2 D16.2 D23.2 D31.2 D37.2 RJ4.2 U2.17 | length 15175.2
  Top Layer w10: v1(2339.34,3366.43) v1@10412.94,3366.43
  Bottom Layer w7: RJ4.2@10822.08,2035.54 10822.08,2003.39 10934.09,1891.38 U2.17@10934.09,1704.68
  Bottom Layer w10: D4.2@2339.34,3665.1 v1(2339.34,3366.43) 2339.34,3264.31 2046.27,2971.24 D10.2@2046.27,2863.47 2046.27,2343.49 2130.6,2259.16 D16.2@2312.37,2259.16 2312.37,1728.74 2389.19,1651.91 D23.2@2511.87,1651.91 2511.87,1142.13 2608.78,1045.22 D31.2@2788.24,1045.22 2788.24,672.31 3019.69,440.87 D37.2@4101.36,440.87 ; v1@10407.02,3366.43 10407.02,3366.25 10407.02,2266.9 10573.59,2100.34 10731.18,2100.34 10795.99,2035.54 RJ4.2@10822.08,2035.54
  other v1: 10407.96,3366.25
CL4: D5.2 D11.2 D17.2 D25.2 D32.2 D38.2 RJ5.2 U2.12 | length 14919.6
  Top Layer w10: v1@3116.73,1582.28 3218.84,1684.39 8745.09,1684.39 8894.4,1833.7 10317.48,1833.7 v1(10476.53,1992.75)
  Bottom Layer w7: v1(10476.53,1992.75) 10662.25,1992.75 10672.53,2003.04 RJ5.2@10672.53,2031.32 10715.09,2031.32 10766.54,1979.86 10766.54,1856.87 10865.19,1758.22 U2.12@10865.19,1704.68
  Bottom Layer w10: D5.2@2936.47,3664.15 2936.47,3307.45 2649.36,3020.34 D11.2@2649.36,2863.47 2649.36,2360.03 2750.23,2259.16 D17.2@2920.91,2259.16 2920.91,1706.73 2975.72,1651.91 D25.2@3118.56,1651.91 3118.56,1175.03 3248.37,1045.22 D32.2@3395.27,1045.22 3395.27,795.17 3558.01,632.43 6261.12,632.43 6354.02,539.53 D38.2@6354.02,440.87
  other v1: 3118.28,1587
CL5: D6.2 D12.2 D18.2 D27.2 D33.2 D39.2 RJ6.2 U2.11 | length 14685.4
  Top Layer w10: v1@3719.27,1574.21 3806.28,1661.22 8776.92,1661.22 8922.3,1806.59 10361.27,1806.59 v1(10478.2,1923.52)
  Bottom Layer w7: v1@10478.2,1923.38 10667.27,1923.38 10672.53,1928.65 RJ6.2@10672.53,1959.77 10726.51,1959.77 10748.47,1937.81 10748.47,1840.68 10851.41,1737.73 U2.11@10851.41,1704.68
  Bottom Layer w10: D6.2@3970.6,3664.02 3677.64,3664.02 3257.08,3243.46 D12.2@3257.08,2863.47 3257.08,2374.18 3372.1,2259.16 D18.2@3526.27,2259.16 3526.27,1727.72 3602.08,1651.91 D27.2@3722.2,1651.91 3722.2,1197.12 3874.09,1045.22 D33.2@3997.43,1045.22 3997.43,854.21 4148.88,702.76 7004.33,702.76 7113.58,593.51 D39.2@7113.58,440.87
  other v1: 3724.12,1578.27
CL6: D40.2 D47.2 D54.2 D61.2 D68.2 RJ7.2 U2.10 | length 10475.7
  Top Layer w10: v1@4334.92,1563.38 4409.18,1637.64 8811.47,1637.64 8941.12,1767.29 10390.87,1767.29 v1(10475.87,1852.28)
  Bottom Layer w7: v1@10475.87,1852.62 10664.67,1852.62 10672.53,1860.49 RJ7.2@10672.53,1888.22 10710.97,1888.22 10730.26,1868.92 10730.26,1752.04 10814.58,1667.72 U2.10@10841.57,1667.72
  Bottom Layer w10: D40.2@4576.32,3664.02 4345.53,3664.02 3858.09,3176.58 D47.2@3858.09,2863.47 3858.09,2328.7 3927.64,2259.16 D54.2@4129.96,2259.16 4129.96,1700.79 4184.14,1646.61 D61.2@4332.3,1646.61 4332.3,1163.77 4450.85,1045.22 D68.2@4607.14,1045.22
  other v1: 4333.99,1564.33
CL7: D41.2 D48.2 D55.2 D62.2 D69.2 D74.2 RJ8.2 U2.9 | length 12894.9
  Top Layer w10: v1@4938.68,1558.47 4996.68,1616.46 8837,1616.46 8960.72,1740.18 10431,1740.18 v1(10471.54,1780.72)
  Bottom Layer w7: v1@10471.54,1780.42 10662.22,1780.42 10672.53,1790.73 RJ8.2@10672.53,1816.66 10698.07,1816.66 10713.65,1801.07 10713.65,1733.66 10793.37,1653.94 U2.9@10841.57,1653.94
  Bottom Layer w10: D41.2@5185.81,3664.02 4996.11,3664.02 4464.85,3132.77 D48.2@4464.85,2863.47 4464.85,2395.07 4600.76,2259.16 D55.2@4734.14,2259.16 4734.14,1735.7 4819.76,1650.08 D62.2@4937.11,1650.08 4937.11,1154.46 5046.35,1045.22 D69.2@5212.73,1045.22 5212.73,860.84 5299.69,773.88 7789.07,773.88 7910.91,652.04 D74.2@7910.91,440.87
  other v1: 4937.6,1559.46
CL8: D42.2 D49.2 D56.2 D63.2 D70.2 D75.2 RJ9.2 U2.8 | length 12382
  Top Layer w10: v1@5539.4,1549.56 5581.03,1591.2 8864.66,1591.2 8982.29,1708.83 v1(10473.87,1708.83)
  Bottom Layer w7: v1@10473.87,1708.07 10661.74,1708.07 10672.53,1718.86 RJ9.2@10672.53,1743.82 ; RJ9.2@10671.57,1744.78 RJ9.2@10672.53,1743.82 ; RJ9.2@10672.53,1745.11 RJ9.2@10672.53,1743.82 ; U2.8@10841.57,1640.16 10776.19,1640.16 RJ9.2@10672.53,1743.82
  Bottom Layer w10: D42.2@5795.07,3664.02 5491.62,3664.02 5070.47,3242.87 D49.2@5070.47,2863.47 5070.47,2374.04 5185.35,2259.16 D56.2@5342.8,2259.16 5342.8,1765.34 5455.67,1652.47 D63.2@5539.81,1652.47 5539.81,1225.73 5720.32,1045.22 D70.2@5816.55,1045.22 5816.55,898.1 5884.31,830.34 8527.72,830.34 8671.21,686.85 D75.2@8671.21,440.87
  other v1: 5540.52,1552.44
CL9: D43.2 D50.2 D57.2 D64.2 D71.2 RJ10.2 U2.7 | length 9072.1
  Top Layer w10: v1@6140.37,1534.43 6176.91,1570.96 8899.43,1570.96 9006.35,1677.88 10461.39,1677.88 v1(10478.82,1660.46)
  Bottom Layer w7: v1@10475.34,1663.94 v1(10478.82,1660.46) 10511.29,1627.99 10660.27,1627.99 10672.53,1640.25 RJ10.2@10672.53,1673.55 10702.89,1673.55 10750.06,1626.38 U2.7@10841.57,1626.38
  Bottom Layer w10: D71.2@6415.65,1045.22 6224.86,1045.22 6143.38,1126.7 D64.2@6143.38,1652.04 5988.68,1652.04 5945.6,1695.12 D57.2@5945.6,2259.16 5773.99,2259.16 5664.26,2368.9 D50.2@5664.26,2863.47 5664.26,3198.64 5960.83,3495.22 6795.67,3495.22 6885.94,3585.49 D43.2@6885.94,3664.02
  other v1: 6142.72,1539.32
CL10: D44.2 D51.2 D58.2 D65.2 D72.2 RJ11.2 U2.5 | length 8313
  Top Layer w10: v1@6743.09,1533.71 6743.69,1534.31 v1(10461.51,1534.31)
  Bottom Layer w7: v1(10461.51,1534.31) 10550.53,1534.31 10556.32,1528.53 10660.7,1528.53 10671.57,1539.4 RJ11.2@10671.57,1566.03 10704.36,1598.83 U2.5@10841.57,1598.83
  Bottom Layer w10: D72.2@7021.13,1045.22 6838.02,1045.22 6744.15,1139.1 D65.2@6744.15,1651.91 6656.11,1651.91 6556.44,1751.59 D58.2@6556.44,2259.16 6396.86,2259.16 6276.92,2379.1 D51.2@6276.92,2863.47 6276.92,3149.56 6520.28,3392.92 7345.89,3392.92 7494.2,3541.24 D44.2@7494.2,3664.02
  other v1: 6744.52,1532.52
CL11: D45.2 D52.2 D59.2 D66.2 D73.2 RJ12.2 U2.30 | length 10988.4
  Bottom Layer w7: 8261.49,4324.14 10244.43,4324.14 10718.1,3850.47 11251.71,3850.47 11379.68,3722.5 11379.68,1900.39 11326.79,1847.5 11213.89,1847.5 11202.56,1836.17 11202.56,1812.09 11166.98,1812.09 11145.05,1790.16 11145.05,1651.62 11092.25,1598.83 U2.30@11039.89,1598.83
  Bottom Layer w10: D73.2@8026.22,1045.22 7522.3,1045.22 7353.53,1213.99 D66.2@7353.53,1651.91 7242.18,1651.91 7159.14,1734.95 D59.2@7159.14,2259.16 6993.46,2259.16 6880.5,2372.12 D52.2@6880.5,2863.47 6880.5,3080.14 7060.85,3260.5 7839.22,3260.5 8095.22,3516.49 D45.2@8095.22,3664.02 8095.22,4157.87 8261.49,4324.14
CL12: D46.2 D53.2 D60.2 D67.2 RJ13.2 U2.29 | length 10131
  Bottom Layer w7: D67.2@8569.42,2261.92 D67.2@8572.18,2259.16 ; 8698.27,4197.46 8811.96,4311.14 10235.55,4311.14 10714.6,3832.1 11243,3832.1 11366.68,3708.43 11366.68,1953.04 11332.08,1918.44 11209.86,1918.44 11202.56,1911.15 RJ13.2@11202.56,1883.66 ; U2.29@11039.89,1612.6 11087.65,1612.6 11131.33,1656.29 11131.33,1853.13 11161.87,1883.66 RJ13.2@11202.56,1883.66 ; RJ13.2@11202.56,1882.98 RJ13.2@11202.56,1883.66
  Bottom Layer w10: D53.2@7487.3,2863.47 7487.3,2379.21 7607.34,2259.16 D60.2@7759.08,2259.16 7759.08,3094.36 8328.75,3664.02 D46.2@8698.27,3664.02 ; D67.2@8572.18,2259.16 8572.18,2724.79 8698.27,2850.88 D46.2@8698.27,3664.02 ; 8698.27,4197.46 D46.2@8698.27,3664.02
CL13: D79.2 D86.2 RJ14.2 U2.28 | length 7457.9
  Top Layer w10: v1(8380.93,3527) v1@9510.02,3527
  Bottom Layer w7: v1(9510.02,3527.72) 9510.02,3688.66 9633.27,3811.91 11238.4,3811.91 11353.68,3696.63 11353.68,2021.43 11323.23,1990.98 11209.56,1990.98 11202.56,1983.98 11202.56,1955.24 11162.18,1955.24 11116.55,1909.61 11116.55,1659.89 11083.04,1626.38 U2.28@11039.89,1626.38
  Bottom Layer w10: D86.2@8296.56,1651.91 8296.56,2481.42 8380.15,2565.01 D79.2@8380.15,2863.47 v1@8380.15,3527
CL14: D76.2 D80.2 D83.2 D88.2 RJ15.2 U2.27 | length 8329
  Top Layer w10: v1(9300.89,2142.44) 9300.94,2142.49 v1(9581.65,2142.49)
  Bottom Layer w7: D76.2@9584.83,3664.02 9584.83,3731.42 9647.88,3794.47 11227.08,3794.47 11340.68,3680.88 11340.68,2081.96 11321.42,2062.7 11210.78,2062.7 11202.59,2054.51 11202.59,2026.86 11170.62,2026.86 11103.07,1959.32 11103.07,1664.8 11078.44,1640.16 U2.27@11039.89,1640.16
  Bottom Layer w10: v1(9300.89,2142.44) 8866.99,1708.54 8866.99,871.61 9297.73,440.87 D88.2@9590.87,440.87 ; v1(9581.65,2142.49) D83.2@9581.65,2259.16 9590.43,2267.94 D80.2@9590.43,2863.47 9584.83,2869.07 D76.2@9584.83,3664.02
CL15: D77.2 D81.2 D84.2 D87.2 D89.2 RJ16.2 U2.26 | length 9647.7
  Top Layer w10: v1@9285.18,2203.24 v1(10190.06,2203.24)
  Bottom Layer w7: D77.2@10187.44,3664.02 10187.44,3748.85 10214.38,3775.79 11216.3,3775.79 11327.59,3664.49 11327.59,2151.32 11310.8,2134.52 11210.05,2134.52 11201.94,2126.41 RJ16.2@11201.94,2098.32 ; U2.26@11039.89,1653.94 11071.49,1653.94 11088.9,1671.36 11088.9,1985.28 RJ16.2@11201.94,2098.32 ; RJ16.2@11201.94,2097.64 RJ16.2@11201.94,2098.32
  Bottom Layer w10: v1(9285.18,2204.8) 8819.6,1739.22 8819.6,861.32 9309.65,371.27 10176.89,371.27 10193.66,388.04 D89.2@10193.66,437.55 10193.66,1044.99 D87.2@10193.89,1045.22 ; D77.2@10187.44,3664.02 10187.44,3513.83 10199.39,3501.88 D81.2@10199.39,2863.47 10199.39,2461.28 10188.64,2450.54 D84.2@10188.64,2259.16 v1@10188.64,2198.32
CL16: D78.2 D82.2 D85.2 D90.2 RJ17.2 U2.25 | length 4851
  Top Layer w10: v1@10578.34,1355.4 10652.02,1355.4 10703.02,1406.4 v1@10703.02,2258.24 ; v1@10701.27,2259.99 v1@10703.02,2258.24 ; v1(10703.02,2259.99) v1@10703.02,2258.24 ; v1@10706.93,2254.33 v1@10703.02,2258.24
  Bottom Layer w7: 10798.74,2450.4 10809.62,2461.28 ; 10798.74,2461.28 10809.62,2461.28 ; 10798.74,2475.17 10798.74,2472.16 10809.62,2461.28 ; U2.25@11039.89,1667.72 11064.87,1667.72 11075.44,1678.29 11075.44,1998.48 11159.86,2082.9 11159.86,2128.01 RJ17.2@11201.59,2169.74 ; 10809.62,2461.28 11113.39,2461.28 11202.27,2372.4 RJ17.2@11202.27,2170.42 ; RJ17.2@11201.59,2169.74 RJ17.2@11202.27,2170.42 ; RJ17.2@11201.59,2169.74 RJ17.2@11202.27,2169.74 RJ17.2@11202.27,2170.42
  Bottom Layer w10: v1@10578.34,1355.02 10578.34,542.89 10680.14,441.09 D90.2@10798.26,441.09 ; v1(10703.02,2259.99) 10703.85,2259.16 D85.2@10805.09,2259.16 10798.74,2265.51 10798.74,2450.4 10798.74,2461.28 10798.74,2472.16 ; 10798.74,2475.17 D82.2@10798.74,2863.47 10799.68,2864.41 D78.2@10799.68,3664.02
  other v1: 10578.34,1355.7
NetC3_2: C3.2 D22.2 D24.1 U1.2 | length 742
  Bottom Layer w20: 9858.53,1510.2 9858.53,1508.02 ; U1.2@9904.01,1492.78 9873.77,1492.78 ; D24.1@10039.49,1358.69 10039.38,1358.58 C3.2@9901.41,1358.58 9874.35,1358.58 9858.53,1374.4 9858.53,1477.53 ; D22.2@10049.12,1677.06 10049.12,1601.96 10034.3,1587.14 9894.74,1587.14 9858.53,1550.93 9858.53,1508.02 ; 9858.53,1477.53 9858.53,1492.04 ; 9858.53,1477.53 9873.77,1492.78 ; 9858.53,1492.04 9858.53,1508.02 ; 9858.53,1492.04 9859.26,1492.78 9873.77,1492.78 ; 9858.53,1508.02 9873.77,1492.78
NetC10_1: C10.1 C11.1 C12.1 D26.1 L4.2 R131.1 | length 655.5
  Bottom Layer w30: L4.2@9374.78,1337.41 9374.78,1249.72 R131.1@9373.45,1248.39 9426.42,1248.39 9444.56,1230.25 C10.1@9444.56,1170.04 9444.56,995.5 C12.1@9448.12,991.93 ; C12.1@9448.44,991.61 C12.1@9448.23,991.82 C12.1@9448.12,991.93 ; D26.1@9583.84,879.92 9582.64,881.12 C11.1@9448.12,881.12 C12.1@9448.12,991.93
NetC10_2: C10.2 R131.2 R133.2 U3.5 | length 590.4
  Bottom Layer w20: U3.5@9133.76,1537.45 9165.75,1537.45 9181.35,1521.85 9181.35,1285.89 9218.85,1248.39 R131.2@9312.82,1248.39 9313.87,1247.34 R133.2@9313.87,1171.89 9315.72,1170.04 C10.2@9389.56,1170.04
NetD1_1: D1.1 S1.2 | length 145.5
  Top Layer w10: S1.2@339.9,3806.65 S1.2@339.9,3793.8 339.9,3744.95 v1(341.44,3743.41)
  Bottom Layer w10: D1.1@340.22,3664.02 v1@340.22,3745.62
NetD2_1: D2.1 S2.2 | length 137.5
  Top Layer w10: v1@1233.77,3727.11 S2.2@1233.77,3793.8
  Bottom Layer w10: D2.1@1235.34,3664.02 v1(1235.34,3734.86)
NetD3_1: D3.1 S3.2 | length 130.1
  Top Layer w10: v1(1837.53,3742.32) 1838.31,3743.1 S3.2@1838.31,3793.8
  Bottom Layer w10: D3.1@1837.53,3664.02 v1(1837.53,3742.32)
NetD4_1: D4.1 S4.2 | length 130.4
  Top Layer w10: S4.2@2442.84,3793.8 2442.84,3739.32 v1(2444.25,3737.91)
  Bottom Layer w10: D4.1@2444.25,3664.02 v1(2444.25,3737.91)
